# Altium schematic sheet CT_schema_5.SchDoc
size 293 x 134 mm
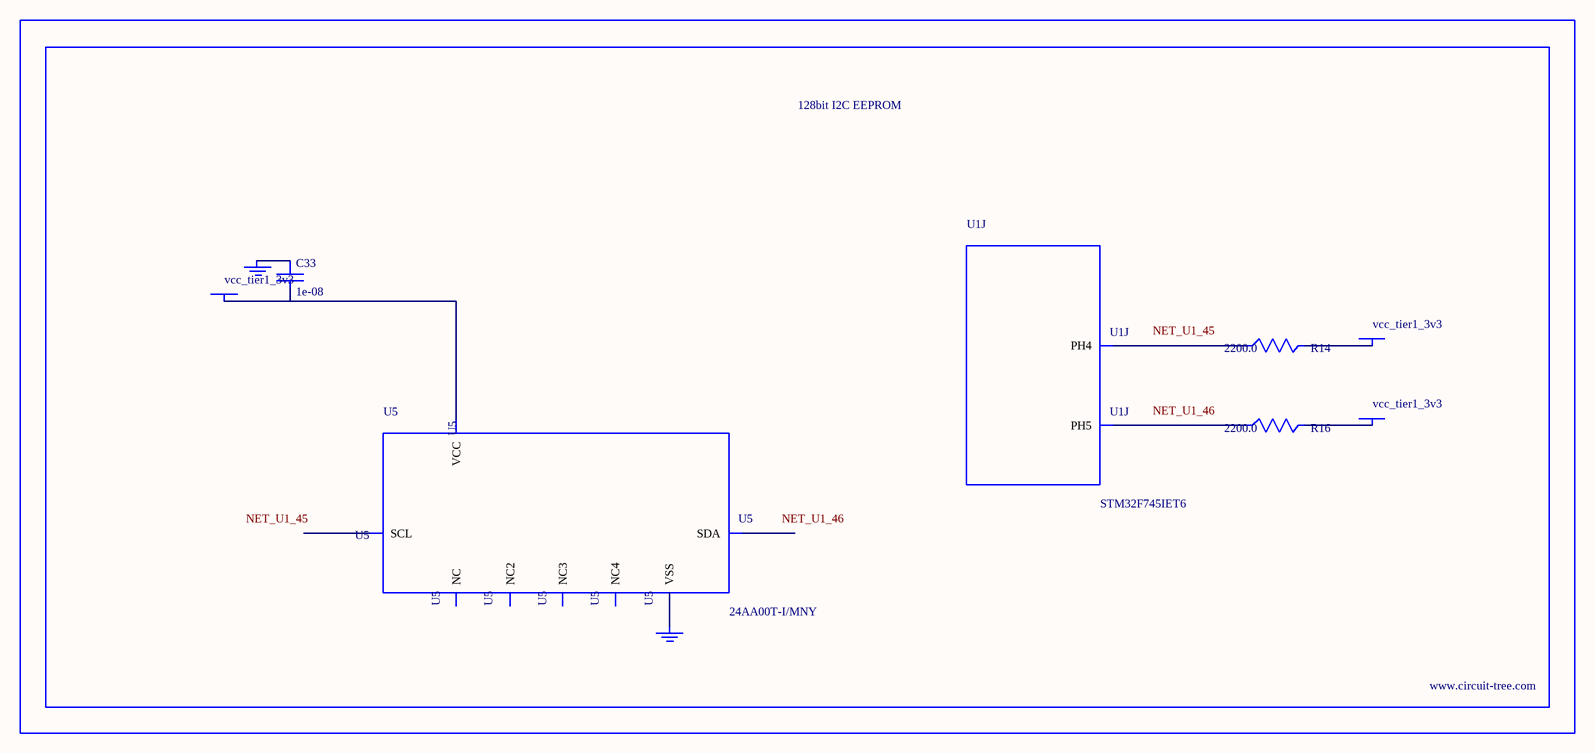
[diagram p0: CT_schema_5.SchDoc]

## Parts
BORDER4  (no value)
C33  1e-08  [C0402]
GND_INSTANCE_4_0  (no value)
GND_INSTANCE_4_1  (no value)
POWER_INSTANCE_4_0  vcc_tier1_3v3
POWER_INSTANCE_4_1  vcc_tier1_3v3
POWER_INSTANCE_4_2  vcc_tier1_3v3
R14  2200.0  [R0603]
R16  2200.0  [R0603]
U1  STM32F745IET6  [LQFP176]  (part J of 14)
U5  24AA00T-I/MNY  [TDFN-8/6MM]

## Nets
NetC33_1: C33.1 GND_INSTANCE_4_0.0(GND)
NetC33_2: C33.2 POWER_INSTANCE_4_0.0(PWR) U5.8(VCC)
NetGND_INSTANCE_4_1_0: GND_INSTANCE_4_1.0(GND) U5.4(VSS)
NetPOWER_INSTANCE_4_1_0: POWER_INSTANCE_4_1.0(PWR) R14.2
NetPOWER_INSTANCE_4_2_0: POWER_INSTANCE_4_2.0(PWR) R16.2
NetR14_1: R14.1 U1.45(PH4)
NetR16_1: R16.1 U1.46(PH5)

Not connected (* = marked no-connect by the designer): U5 1(NC) 2(NC2) 3(NC3) 5(SDA) 6(SCL) 7(NC4)

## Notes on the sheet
- Labels drawn without touching a wire or pin: NET_U1_45, NET_U1_46

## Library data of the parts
BORDER4 = BORDER_PAGE4
C33 = C0402C103K3RAC
GND_INSTANCE_4_0 GND_INSTANCE_4_1 = GND
POWER_INSTANCE_4_0-POWER_INSTANCE_4_2 = PWR
R14 R16 = RC0603JR-072K2L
